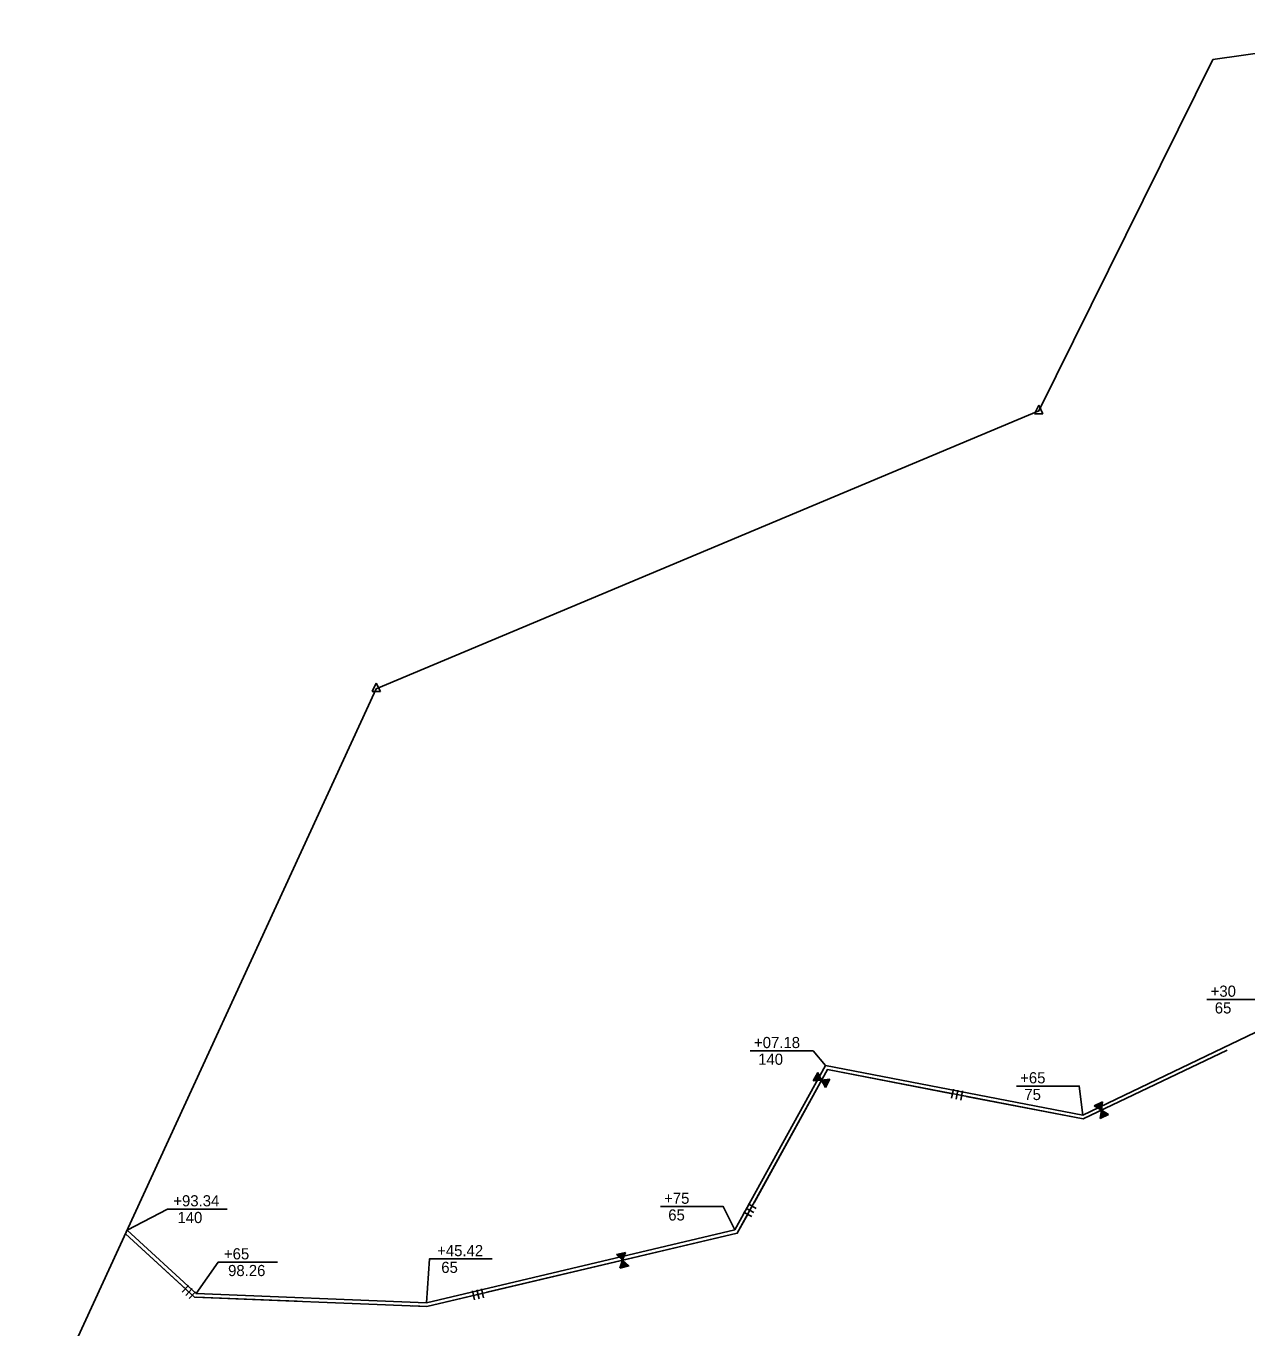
# Model space of a CAD drawing. Extents: x 979729 to 993523, y 1834148 to 1845433.
# Drawn here: x 981738 to 982395, y 1841880 to 1842581 of the extents above; entities that cross this region are included whole.
import ezdxf

# ---------------------------------------------------------------- set-up
doc = ezdxf.new("R2010")
doc.units = 0
for name, color, linetype in [('42', 7, 'Continuous'), ('51', 7, 'Continuous'), ('R_Draft', 7, 'Continuous'), ('S_EXIST_ROW', 7, 'Continuous')]:
    doc.layers.add(name, color=color, linetype=linetype)

msp = doc.modelspace()

# ---------------------------------------------------------------- linework, layer by layer
at = {"layer": '42'}
for p, q in [((982384.78, 1842029.39), (982307.33, 1841992.34)), ((982169.65, 1842018.91), (982121.14, 1841930.83)), ((982307.33, 1841992.34), (982169.65, 1842018.91)), ((982166.55, 1842013.28), (982162.06, 1842012.9)), ((982166.48, 1842013.36), (982162.1, 1842012.99)), ((982166.31, 1842013.59), (982162.25, 1842013.25)), ((982166.23, 1842013.84), (982162.39, 1842013.51)), ((982166.09, 1842014.08), (982162.54, 1842013.78)), ((982165.98, 1842014.32), (982162.68, 1842014.04)), ((982165.81, 1842014.55), (982162.83, 1842014.3)), ((982165.74, 1842014.8), (982162.97, 1842014.57)), ((982165.56, 1842015.04), (982163.12, 1842014.83)), ((982165.46, 1842015.28), (982163.26, 1842015.09)), ((982165.24, 1842015.76), (982163.55, 1842015.62)), ((982165.28, 1842015.51), (982163.57, 1842015.37)), ((982165.13, 1842016), (982163.7, 1842015.88)), ((982164.99, 1842016.24), (982163.84, 1842016.14)), ((982164.84, 1842016.48), (982163.99, 1842016.41)), ((982164.74, 1842016.72), (982164.13, 1842016.67)), ((982164.59, 1842016.96), (982164.28, 1842016.93)), ((982164.49, 1842017.2), (982164.42, 1842017.2)), ((982164.47, 1842017.28), (982166.55, 1842013.28)), ((982171.04, 1842013.66), (982166.55, 1842013.28)), ((982166.55, 1842013.28), (982168.63, 1842009.28)), ((982166.65, 1842013.27), (982168.67, 1842009.37)), ((982166.94, 1842013.25), (982168.82, 1842009.63)), ((982167.19, 1842013.32), (982168.96, 1842009.9)), ((982167.47, 1842013.32), (982169.11, 1842010.16)), ((982167.72, 1842013.36), (982169.25, 1842010.42)), ((982168.02, 1842013.34), (982169.4, 1842010.68)), ((982168.26, 1842013.41), (982169.54, 1842010.95)), ((982168.56, 1842013.39), (982169.69, 1842011.21)), ((982168.82, 1842013.43), (982169.83, 1842011.47)), ((982169.11, 1842013.4), (982169.9, 1842011.88)), ((982169.34, 1842013.5), (982170.12, 1842012)), ((982169.6, 1842013.54), (982170.27, 1842012.26)), ((982169.88, 1842013.55), (982170.41, 1842012.53)), ((982170.16, 1842013.55), (982170.56, 1842012.79)), ((982170.42, 1842013.59), (982170.7, 1842013.05)), ((982170.7, 1842013.6), (982170.85, 1842013.32)), ((982170.96, 1842013.64), (982170.99, 1842013.58)), ((982236.5, 1842003.46), (982237.45, 1842008.37)), ((982238.96, 1842002.99), (982239.91, 1842007.9)), ((982241.41, 1842002.51), (982242.36, 1842007.42)), ((982317.12, 1841997.03), (982313.25, 1841999.33)), ((982317.11, 1841997.12), (982313.34, 1841999.37)), ((982317.11, 1841997.42), (982313.61, 1841999.5)), ((982317.19, 1841997.66), (982313.88, 1841999.63)), ((982317.21, 1841997.94), (982314.15, 1841999.76)), ((982317.27, 1841998.2), (982314.42, 1841999.89)), ((982317.26, 1841998.49), (982314.69, 1842000.02)), ((982317.34, 1841998.73), (982314.96, 1842000.15)), ((982317.34, 1841999.03), (982315.23, 1842000.28)), ((982317.4, 1841999.28), (982315.5, 1842000.41)), ((982317.39, 1841999.58), (982315.92, 1842000.45)), ((982317.5, 1841999.8), (982316.05, 1842000.67)), ((982317.55, 1842000.06), (982316.32, 1842000.8)), ((982317.12, 1841997.03), (982316.48, 1841992.56)), ((982317.19, 1841996.96), (982316.57, 1841992.61)), ((982317.57, 1842000.34), (982316.59, 1842000.93)), ((982317.42, 1841996.77), (982316.84, 1841992.74)), ((982317.59, 1842000.62), (982316.86, 1842001.06)), ((982317.66, 1841996.68), (982317.11, 1841992.87)), ((982317.76, 1842001.49), (982317.12, 1841997.03)), ((982320.99, 1841994.72), (982317.12, 1841997.03)), ((982317.65, 1842000.88), (982317.13, 1842001.19)), ((982317.89, 1841996.52), (982317.38, 1841993)), ((982317.67, 1842001.16), (982317.4, 1842001.32)), ((982318.12, 1841996.41), (982317.66, 1841993.13)), ((982317.73, 1842001.41), (982317.67, 1842001.45)), ((982318.35, 1841996.22), (982317.93, 1841993.25)), ((982318.59, 1841996.13), (982318.2, 1841993.38)), ((982318.81, 1841995.94), (982318.47, 1841993.51)), ((982319.05, 1841995.82), (982318.74, 1841993.64)), ((982319.28, 1841995.63), (982319.03, 1841993.94)), ((982319.52, 1841995.57), (982319.28, 1841993.9)), ((982319.76, 1841995.46), (982319.55, 1841994.03)), ((982319.99, 1841995.3), (982319.82, 1841994.16)), ((982320.22, 1841995.14), (982320.09, 1841994.29)), ((982320.45, 1841995.02), (982320.37, 1841994.42)), ((982320.68, 1841994.86), (982320.64, 1841994.55)), ((982320.92, 1841994.75), (982320.91, 1841994.68)), ((982128.94, 1841939.81), (982124.56, 1841942.22)), ((982130.14, 1841942), (982125.76, 1841944.41)), ((982131.35, 1841944.19), (982126.97, 1841946.6)), ((981829.11, 1841896.37), (981791.87, 1841930.54)), ((982121.14, 1841930.83), (981954.14, 1841891.42)), ((982059.46, 1841916.28), (982056.16, 1841919.35)), ((982059.47, 1841916.38), (982056.26, 1841919.38)), ((982059.53, 1841916.66), (982056.55, 1841919.44)), ((982059.66, 1841916.88), (982056.84, 1841919.51)), ((982059.74, 1841917.15), (982057.14, 1841919.58)), ((982059.85, 1841917.39), (982057.43, 1841919.65)), ((982059.91, 1841917.68), (982057.72, 1841919.72)), ((982060.04, 1841917.9), (982058.01, 1841919.79)), ((982060.1, 1841918.18), (982058.31, 1841919.86)), ((982060.21, 1841918.42), (982058.6, 1841919.93)), ((982060.26, 1841918.72), (982059.01, 1841919.88)), ((982060.42, 1841918.91), (982059.18, 1841920.07)), ((982061.03, 1841920.5), (982059.46, 1841916.28)), ((982060.53, 1841919.15), (982059.48, 1841920.13)), ((982060.61, 1841919.42), (982059.77, 1841920.2)), ((982060.69, 1841919.69), (982060.06, 1841920.27)), ((982060.8, 1841919.93), (982060.35, 1841920.34)), ((982060.88, 1841920.19), (982060.65, 1841920.41)), ((982060.99, 1841920.43), (982060.94, 1841920.48)), ((982059.46, 1841916.28), (982057.88, 1841912.05)), ((982059.51, 1841916.2), (982057.98, 1841912.08)), ((982059.7, 1841915.97), (982058.27, 1841912.15)), ((982059.91, 1841915.83), (982058.57, 1841912.21)), ((982060.1, 1841915.62), (982058.86, 1841912.28)), ((982060.31, 1841915.46), (982059.15, 1841912.35)), ((982060.49, 1841915.23), (982059.44, 1841912.42)), ((982062.75, 1841913.2), (982059.46, 1841916.28)), ((982060.7, 1841915.09), (982059.74, 1841912.49)), ((982060.88, 1841914.86), (982060.03, 1841912.56)), ((982061.09, 1841914.69), (982060.32, 1841912.63)), ((982061.27, 1841914.45), (982060.67, 1841912.85)), ((982061.5, 1841914.35), (982060.91, 1841912.77)), ((982061.7, 1841914.18), (982061.2, 1841912.84)), ((982061.89, 1841913.98), (982061.49, 1841912.9)), ((982062.08, 1841913.78), (982061.78, 1841912.97)), ((982062.29, 1841913.61), (982062.08, 1841913.04)), ((982062.48, 1841913.41), (982062.37, 1841913.11)), ((982062.68, 1841913.24), (982062.66, 1841913.18)), ((981822.51, 1841899.04), (981825.89, 1841902.72)), ((981824.35, 1841897.35), (981827.73, 1841901.03)), ((981826.2, 1841895.66), (981829.58, 1841899.34)), ((981979.74, 1841894.9), (981978.59, 1841899.76)), ((981982.17, 1841895.47), (981981.02, 1841900.34)), ((981984.6, 1841896.04), (981983.45, 1841900.91)), ((981954.14, 1841891.42), (981829.11, 1841896.37))]:
    msp.add_line(p, q, dxfattribs=at)
for points in [[(982384.78, 1842029.39), (982307.33, 1841992.34), (982244.34, 1842004.5)], [(982236.98, 1842005.92), (982169.65, 1842018.91), (982130.36, 1841947.59)], [(982164.47, 1842017.28), (982162.06, 1842012.9)], [(982171.04, 1842013.66), (982168.63, 1842009.28)], [(982317.76, 1842001.49), (982313.25, 1841999.33)], [(982320.99, 1841994.72), (982316.48, 1841992.56)], [(982126.75, 1841941.02), (982121.14, 1841930.83), (981986.46, 1841899.05)], [(981824.2, 1841900.88), (981791.87, 1841930.54)], [(982061.03, 1841920.5), (982056.16, 1841919.35)], [(982062.75, 1841913.2), (982057.88, 1841912.05)], [(981884.33, 1841894.19), (981829.95, 1841896.34)], [(981979.16, 1841897.33), (981954.14, 1841891.42), (981946.56, 1841891.72)]]:
    msp.add_lwpolyline(points, dxfattribs=at)
at = {"layer": '51'}
for points in [[(982610.33, 1842460.58), (982522.85, 1842272.24), (982451.95, 1842249.25), (982452.61, 1842216.09), (982413.33, 1842045.26), (982307.06, 1841994.43), (982168.6, 1842021.15)], [(982168.6, 1842021.15), (982119.81, 1841932.58), (981953.95, 1841893.43)], [(981953.95, 1841893.43), (981829.92, 1841898.34), (981792.75, 1841932.45)]]:
    msp.add_lwpolyline(points, dxfattribs=at)
at = {"layer": 'R_Draft'}
for p, q in [((982373.87, 1842056.6), (982401.7, 1842056.6)), ((982128.14, 1842028.97), (982155.97, 1842028.97)), ((982271.39, 1842009.99), (982299.21, 1842009.99)), ((981820.47, 1841943.8), (981846.56, 1841943.8)), ((982079.77, 1841945.17), (982107.59, 1841945.17)), ((981847.73, 1841915.26), (981873.81, 1841915.26)), ((981961.48, 1841916.98), (981989.3, 1841916.98))]:
    msp.add_line(p, q, dxfattribs=at)
for points in [[(982168.6, 1842021.15), (982161.97, 1842028.97), (982155.97, 1842028.97)], [(982307.06, 1841994.43), (982305.21, 1842009.99), (982299.21, 1842009.99)], [(981792.75, 1841932.45), (981814.47, 1841943.8), (981820.47, 1841943.8)], [(982119.81, 1841932.58), (982113.59, 1841945.17), (982107.59, 1841945.17)], [(981829.92, 1841898.34), (981841.73, 1841915.26), (981847.73, 1841915.26)], [(981953.95, 1841893.43), (981955.48, 1841916.98), (981961.48, 1841916.98)]]:
    msp.add_lwpolyline(points, dxfattribs=at)
at = {"layer": 'S_EXIST_ROW'}
for p, q in [((982377.14, 1842562.53), (982502.45, 1842580.53)), ((982283.38, 1842373.42), (982377.14, 1842562.53)), ((982283.39, 1842376.44), (982281.13, 1842371.9)), ((982283.39, 1842376.44), (982285.62, 1842371.9)), ((981926.9, 1842223.83), (982283.38, 1842373.42)), ((982281.13, 1842371.9), (982285.62, 1842371.9)), ((982283.38, 1842373.42), (982283.38, 1842373.42)), ((981738.4, 1841814.4), (981926.9, 1842223.83)), ((981926.91, 1842226.86), (981924.65, 1842222.32)), ((981924.65, 1842222.32), (981929.14, 1842222.32)), ((981926.9, 1842223.83), (981926.9, 1842223.83)), ((981926.91, 1842226.86), (981929.14, 1842222.32))]:
    msp.add_line(p, q, dxfattribs=at)
for centre, radius in [((982283.38, 1842373.42), 0.0768), ((982283.38, 1842373.42), 0.0384), ((981926.9, 1842223.83), 0.0768), ((981926.9, 1842223.83), 0.0384)]:
    msp.add_circle(centre, radius, dxfattribs=at)

# ---------------------------------------------------------------- texts
at = {"layer": 'R_Draft'}
for s, p in [('+30', (982375.89, 1842058.1)), (' 65', (982375.89, 1842049.1)), ('+07.18', (982130.16, 1842030.47)), (' 140', (982130.16, 1842021.47)), ('+65', (982273.4, 1842011.49)), (' 75', (982273.4, 1842002.49)), ('+93.34', (981817.65, 1841945.3)), ('+75', (982081.78, 1841946.67)), (' 140', (981817.65, 1841936.3)), (' 65', (982081.78, 1841937.67)), ('+65', (981844.9, 1841916.76)), ('+45.42', (981959.63, 1841918.48)), (' 98.26', (981844.9, 1841907.76)), (' 65', (981959.63, 1841909.48))]:
    msp.add_text(s, height=6, rotation=360, dxfattribs=at).set_placement(p)

doc.saveas('drawing.dxf')
